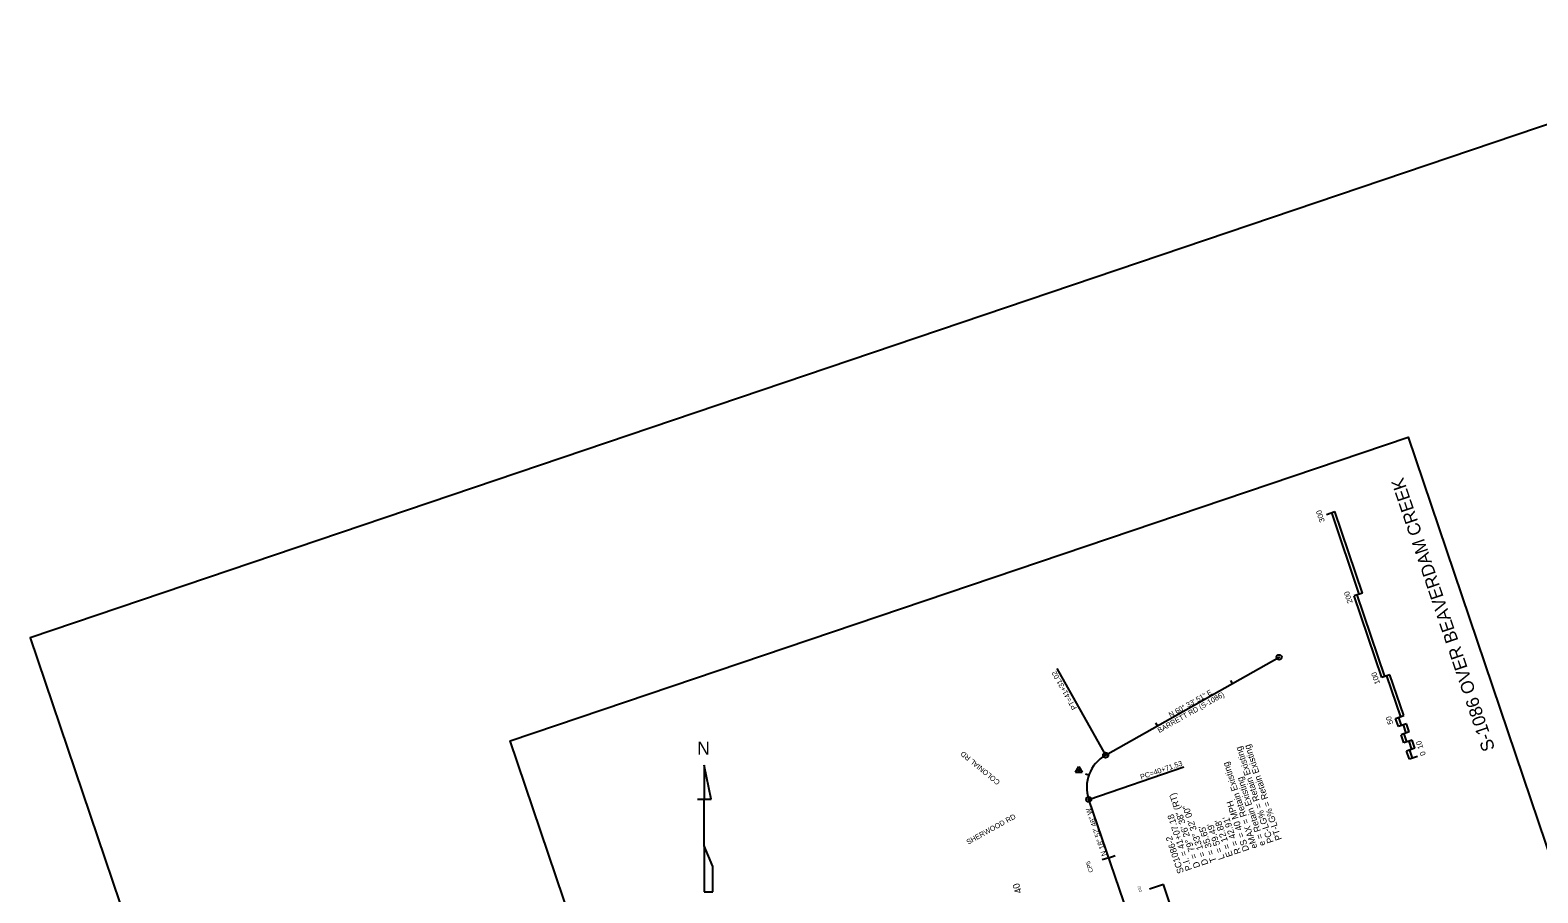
# Model space of a CAD drawing. Extents: x 1509010 to 1932418, y 898655 to 1204101.
# Drawn here: x 1929181 to 1930930, y 1203100 to 1204101 of the extents above; entities that cross this region are included whole.
import ezdxf

# ---------------------------------------------------------------- set-up
doc = ezdxf.new("R2010")
doc.units = 0
for name, color, linetype in [('BR_PROPOSED_TRAVELWAY', 7, 'Continuous'), ('Default', 7, 'Continuous'), ('RD_HC_Cl', 7, 'Continuous'), ('RD_HC_Data', 7, 'Continuous'), ('RD_HC_Data_Tic', 7, 'Continuous'), ('RD_HC_Survey', 7, 'Continuous'), ('RD_HC_TX_Sta50', 7, 'Continuous'), ('RD_PD_ALT1_TX', 7, 'Continuous'), ('RD_PD_CstnLmt_TX', 7, 'Continuous'), ('RD_PD_RW', 7, 'Continuous'), ('RD_SHT_IplotShp', 7, 'Continuous'), ('RD_SMD_Locator', 7, 'Continuous')]:
    doc.layers.add(name, color=color, linetype=linetype)

# ---------------------------------------------------------------- blocks, each defined once
blk = doc.blocks.new('GSC050')
at = {"layer": 'Default'}
for p, q in [((0, -96), (0, 0)), ((0, 0), (96, 0)), ((96, -96), (96, 0)), ((192, -96), (192, 0)), ((192, 0), (288, 0)), ((288, -96), (288, 0)), ((384, -96), (384, 0)), ((384, 0), (480, 0)), ((480, 0), (480, -96)), ((960, -96), (960, 0)), ((960, 0), (1920, 0)), ((1920, -96), (1920, 0)), ((2880, 0), (2880, -96)), ((0, -36), (96, -36)), ((96, -60), (192, -60)), ((96, -96), (192, -96)), ((192, -36), (288, -36)), ((288, -60), (384, -60)), ((288, -96), (384, -96)), ((384, -36), (480, -36)), ((480, -60), (960, -60)), ((480, -96), (960, -96)), ((960, -36), (1920, -36)), ((1920, -60), (2880, -60)), ((1920, -96), (2880, -96))]:
    blk.add_line(p, q, dxfattribs=at)
for s, p in [('50', (434.7951, 42)), ('100', (906.0396, 38)), ('200', (1856.4727, 38)), ('300', (2812.4727, 42)), ('0', (-10.882, -190)), ('10', (68.362, -187.6))]:
    blk.add_text(s, height=60, dxfattribs=at).set_placement(p)

msp = doc.modelspace()

# ---------------------------------------------------------------- linework, layer by layer
at = {"layer": 'BR_PROPOSED_TRAVELWAY'}
msp.add_lwpolyline([(1930314.6, 1201571.4), (1929737.8, 1203276.5), (1930779.7, 1203629), (1931356.6, 1201923.9)], close=True, dxfattribs=at)
at = {"layer": 'RD_HC_Cl'}
for p, q in [((1930428.7, 1203259.8), (1930630, 1203373.4)), ((1930484.5, 1202988.1), (1930409.1, 1203208.5))]:
    msp.add_line(p, q, dxfattribs=at)
msp.add_arc((1930449.7, 1203222.4), 42.9, 119.4357, 198.8796, dxfattribs=at)
at = {"layer": 'RD_HC_Data'}
for p, q in [((1930371.9, 1203360.4), (1930428.7, 1203259.8)), ((1930393.6, 1203239.9), (1930397.6, 1203246.8)), ((1930393.6, 1203239.9), (1930401.6, 1203239.9)), ((1930397.6, 1203246.8), (1930401.6, 1203239.9)), ((1930409.1, 1203208.5), (1930519.3, 1203246.2))]:
    msp.add_line(p, q, dxfattribs=at)
for centre, radius in [((1930630, 1203373.4), 3), ((1930630, 1203373.4), 0.282), ((1930428.7, 1203259.8), 3), ((1930428.7, 1203259.8), 0.282), ((1930397.6, 1203242.2), 0.529), ((1930409.1, 1203208.5), 3), ((1930409.1, 1203208.5), 0.282)]:
    msp.add_circle(centre, radius, dxfattribs=at)
at = {"layer": 'RD_HC_Data_Tic'}
for p, q in [((1930575.8, 1203342.8), (1930573.9, 1203346.3)), ((1930488.7, 1203293.7), (1930486.8, 1203297.1)), ((1930409.2, 1203236.5), (1930405.4, 1203237.8)), ((1930432.3, 1203140.8), (1930424.7, 1203138.2)), ((1930432.3, 1203140.8), (1930439.9, 1203143.4))]:
    msp.add_line(p, q, dxfattribs=at)
at = {"layer": 'RD_PD_ALT1_TX'}
for p, q in [((1929970.9, 1203208.9), (1929963, 1203248.1)), ((1929963, 1203248.1), (1929963, 1203248.1)), ((1929963, 1203248.1), (1929963, 1203208.9)), ((1929955.2, 1203208.9), (1929963, 1203208.9)), ((1929963, 1203154.5), (1929963, 1203208.9)), ((1929963, 1203208.9), (1929970.9, 1203208.9)), ((1929970.9, 1203208.9), (1929970.9, 1203209.4)), ((1929972.8, 1203130.5), (1929963, 1203154.5)), ((1929963, 1203154.5), (1929963, 1203101.1)), ((1929972.8, 1203101.1), (1929972.8, 1203130.8)), ((1929972.8, 1203130.8), (1929972.8, 1203130.5)), ((1929963, 1203101.1), (1929972.8, 1203101.1))]:
    msp.add_line(p, q, dxfattribs=at)
at = {"layer": 'RD_PD_RW'}
for p, q in [((1930495.8, 1203109.7), (1930479.7, 1203104.2)), ((1930531.9, 1203004.2), (1930495.8, 1203109.7))]:
    msp.add_line(p, q, dxfattribs=at)
at = {"layer": 'RD_SHT_IplotShp'}
msp.add_lwpolyline([(1932418.4, 1200691), (1931264.8, 1204101.1), (1929180.8, 1203396.1), (1930334.5, 1199986)], close=True, dxfattribs=at)
at = {"layer": 'RD_SMD_Locator'}
for centre in [(1930630, 1203373.4), (1930428.7, 1203259.8), (1930397.6, 1203242.2), (1930409.1, 1203208.5)]:
    msp.add_circle(centre, 0.15, dxfattribs=at)

# ---------------------------------------------------------------- block references
at = {"layer": 'RD_PD_ALT1_TX', "xscale": 0.10416176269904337, "yscale": 0.10416176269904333, "rotation": 108.69125831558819}
msp.add_blockref('GSC050', (1930781.2, 1203255.1), dxfattribs=at)

# ---------------------------------------------------------------- texts
at = {"layer": 'RD_HC_Data'}
for s, height, rotation, p in [('PT=41+31.02', 6, 119.4357, (1930395.5, 1203314.5)), ('BARRETT RD (S-1086)', 6, 29.4357, (1930491, 1203285.4)), ('N 60%%d 33\' 51" E', 6, 29.4357, (1930504, 1203303.4)), ('PC-LG% = Retain Existing', 7.5, 108.6913, (1930623.9, 1203159.1)), ('PT-LG% = Retain Existing', 7.5, 108.6913, (1930633.4, 1203162.3)), ('COLONIAL RD', 6, 140.6229, (1930306.8, 1203229.3)), ('PC=40+71.53', 6, 18.8796, (1930470, 1203231.4)), ('eMAX = Retain Existing', 7.5, 108.6913, (1930605, 1203152.7)), ('e = Retain Existing', 7.5, 108.6913, (1930614.4, 1203155.9)), ('    = 79%%d 26\' 38" (RT)', 7.5, 108.6913, (1930538.7, 1203130.3)), ('D = 133%%d 32\' 00"', 7.5, 108.6913, (1930548.1, 1203133.5)), ('DS = 40 MPH', 7.5, 108.6913, (1930595.5, 1203149.5)), ('SHERWOOD RD', 6, 29.0046, (1930269.2, 1203155.8)), ('N 18%%d 52\' 46" W', 6, 108.8796, (1930430.2, 1203143.9)), ('P.I. = 41+07.18', 7.5, 108.6913, (1930529.2, 1203127.1)), ("E = 12.88'", 7.5, 108.6913, (1930576.5, 1203143.1)), ("R = 42.91'", 7.5, 108.6913, (1930586, 1203146.3)), ('SC1086-2', 7.5, 108.6913, (1930519.7, 1203123.9)), ("T = 35.65'", 7.5, 108.6913, (1930557.6, 1203136.7)), ("L = 59.49'", 7.5, 108.6913, (1930567.1, 1203139.9)), ('D', 7.5, 108.6913, (1930538.7, 1203130.3))]:
    msp.add_text(s, height=height, rotation=rotation, dxfattribs=at).set_placement(p)
at = {"layer": 'RD_HC_Survey'}
msp.add_text('CP5', height=5, rotation=108.6913, dxfattribs=at).set_placement((1930414.4, 1203124.6))
at = {"layer": 'RD_HC_TX_Sta50'}
msp.add_text('40', height=8, rotation=108.8796, dxfattribs=at).set_placement((1930331.8, 1203100.8))
at = {"layer": 'RD_PD_ALT1_TX'}
msp.add_text('S-1086 OVER BEAVERDAM CREEK', height=15, rotation=108.6913, dxfattribs=at).set_placement((1930880.7, 1203267.2))
msp.add_text('N', height=15, dxfattribs=at).set_placement((1929954.9, 1203260.4))
at = {"layer": 'RD_PD_CstnLmt_TX'}
msp.add_text('16C', height=3, rotation=108.8796, dxfattribs=at).set_placement((1930471, 1203101.3))

doc.saveas('drawing.dxf')
